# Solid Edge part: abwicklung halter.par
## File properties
Author: Administrator
Template: Normal.par
Last saved by: Administrator
Revision: 1
Application: Solid Edge
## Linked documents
bung Abwicklung.par
Halter.psm
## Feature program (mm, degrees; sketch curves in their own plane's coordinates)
part copy "unnamed PartCopy 1"
